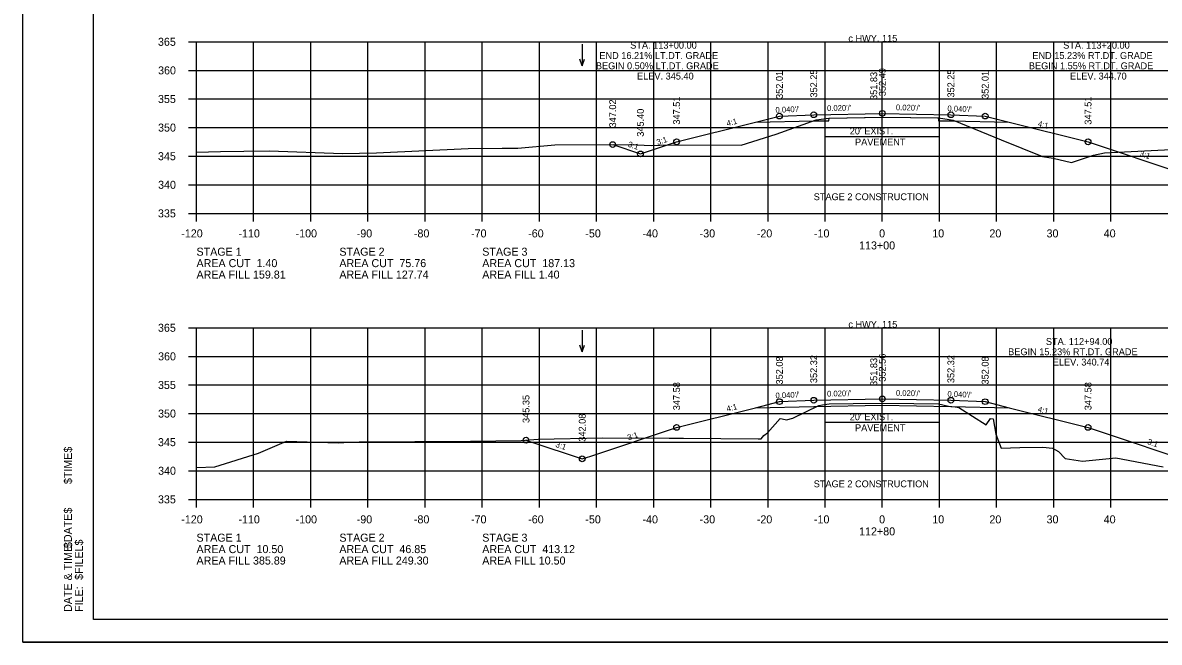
# Model space of a CAD drawing. Extents: x 1630712 to 1632516, y 782146 to 785403.
# Drawn here: x 1632182.6 to 1632381.4, y 784763.3 to 784871.6 of the extents above; entities that cross this region are included whole.
import ezdxf

# ---------------------------------------------------------------- set-up
doc = ezdxf.new("R2010")
doc.units = 0
for name, color, linetype in [('Default', 7, 'Continuous'), ('Notes', 7, 'Continuous'), ('R_Alt Surface', 7, 'Continuous'), ('R_Axis', 7, 'Continuous'), ('R_Axis Annot', 7, 'Continuous'), ('R_Border', 7, 'Continuous'), ('R_Exist Surface', 7, 'Continuous'), ('R_Fin Surface', 7, 'Continuous'), ('R_Grid', 7, 'Continuous'), ('R_No Plot', 7, 'Continuous'), ('R_Water Annot', 7, 'Continuous'), ('R_Xsect Elev', 7, 'Continuous'), ('R_Xsect Slope', 7, 'Continuous')]:
    doc.layers.add(name, color=color, linetype=linetype)

msp = doc.modelspace()

# ---------------------------------------------------------------- linework, layer by layer
at = {"layer": 'Notes'}
for p, q in [((1632322.96, 784850.05), (1632322.96, 784853.45)), ((1632342.96, 784850.05), (1632342.96, 784853.45)), ((1632322.96, 784851.75), (1632342.96, 784851.75)), ((1632322.96, 784800.08), (1632322.96, 784803.48)), ((1632342.96, 784800.08), (1632342.96, 784803.48)), ((1632322.96, 784801.78), (1632342.96, 784801.78))]:
    msp.add_line(p, q, dxfattribs=at)
at = {"layer": 'R_Alt Surface'}
for points in [[(1632310.79, 784854.27), (1632320.96, 784854.47), (1632323.63, 784854.52), (1632323.68, 784854.96), (1632333.09, 784855.14), (1632342.77, 784854.99), (1632342.82, 784854.52), (1632344.96, 784854.47), (1632355.14, 784854.27)], [(1632310.78, 784804.34), (1632320.96, 784804.55), (1632332.96, 784804.79), (1632344.96, 784804.55), (1632355.15, 784804.34)]]:
    msp.add_lwpolyline(points, dxfattribs=at)
at = {"layer": 'R_Axis'}
for p, q in [((1632211.56, 784868.31), (1632212.96, 784868.31)), ((1632212.96, 784838.31), (1632212.96, 784868.31)), ((1632211.56, 784863.31), (1632212.96, 784863.31)), ((1632211.56, 784858.31), (1632212.96, 784858.31)), ((1632211.56, 784853.31), (1632212.96, 784853.31)), ((1632211.56, 784848.31), (1632212.96, 784848.31)), ((1632211.56, 784843.31), (1632212.96, 784843.31)), ((1632211.56, 784838.31), (1632212.96, 784838.31)), ((1632212.96, 784838.31), (1632492.96, 784838.31)), ((1632212.96, 784836.91), (1632212.96, 784838.31)), ((1632222.96, 784836.91), (1632222.96, 784838.31)), ((1632232.96, 784836.91), (1632232.96, 784838.31)), ((1632242.96, 784836.91), (1632242.96, 784838.31)), ((1632252.96, 784836.91), (1632252.96, 784838.31)), ((1632262.96, 784836.91), (1632262.96, 784838.31)), ((1632272.96, 784836.91), (1632272.96, 784838.31)), ((1632282.96, 784836.91), (1632282.96, 784838.31)), ((1632292.96, 784836.91), (1632292.96, 784838.31)), ((1632302.96, 784836.91), (1632302.96, 784838.31)), ((1632312.96, 784836.91), (1632312.96, 784838.31)), ((1632322.96, 784836.91), (1632322.96, 784838.31)), ((1632332.96, 784836.91), (1632332.96, 784838.31)), ((1632342.96, 784836.91), (1632342.96, 784838.31)), ((1632352.96, 784836.91), (1632352.96, 784838.31)), ((1632362.96, 784836.91), (1632362.96, 784838.31)), ((1632372.96, 784836.91), (1632372.96, 784838.31)), ((1632211.56, 784818.31), (1632212.96, 784818.31)), ((1632212.96, 784788.31), (1632212.96, 784818.31)), ((1632211.56, 784813.31), (1632212.96, 784813.31)), ((1632211.56, 784808.31), (1632212.96, 784808.31)), ((1632211.56, 784803.31), (1632212.96, 784803.31)), ((1632211.56, 784798.31), (1632212.96, 784798.31)), ((1632211.56, 784793.31), (1632212.96, 784793.31)), ((1632211.56, 784788.31), (1632212.96, 784788.31)), ((1632212.96, 784788.31), (1632492.96, 784788.31)), ((1632212.96, 784786.91), (1632212.96, 784788.31)), ((1632222.96, 784786.91), (1632222.96, 784788.31)), ((1632232.96, 784786.91), (1632232.96, 784788.31)), ((1632242.96, 784786.91), (1632242.96, 784788.31)), ((1632252.96, 784786.91), (1632252.96, 784788.31)), ((1632262.96, 784786.91), (1632262.96, 784788.31)), ((1632272.96, 784786.91), (1632272.96, 784788.31)), ((1632282.96, 784786.91), (1632282.96, 784788.31)), ((1632292.96, 784786.91), (1632292.96, 784788.31)), ((1632302.96, 784786.91), (1632302.96, 784788.31)), ((1632312.96, 784786.91), (1632312.96, 784788.31)), ((1632322.96, 784786.91), (1632322.96, 784788.31)), ((1632332.96, 784786.91), (1632332.96, 784788.31)), ((1632342.96, 784786.91), (1632342.96, 784788.31)), ((1632352.96, 784786.91), (1632352.96, 784788.31)), ((1632362.96, 784786.91), (1632362.96, 784788.31)), ((1632372.96, 784786.91), (1632372.96, 784788.31))]:
    msp.add_line(p, q, dxfattribs=at)
at = {"layer": 'R_Border'}
for p, q in [((1632194.96, 784767.31), (1632194.96, 784972.77)), ((1632511.14, 784767.31), (1632194.96, 784767.31))]:
    msp.add_line(p, q, dxfattribs=at)
at = {"layer": 'R_Exist Surface'}
for points in [[(1632212.96, 784849.04), (1632217.18, 784849.11), (1632221.23, 784849.16), (1632225.71, 784849.22), (1632238.48, 784848.79), (1632244.48, 784848.88), (1632260.51, 784849.66), (1632266.47, 784849.7), (1632269.19, 784849.73), (1632275.65, 784850.32), (1632288.76, 784850.33), (1632292.5, 784850.16), (1632295.61, 784850.31), (1632308.29, 784850.23), (1632314.39, 784852.16), (1632321.39, 784854.67), (1632323.6, 784854.95), (1632323.68, 784854.96), (1632332.91, 784855.14), (1632333.09, 784855.14), (1632342.61, 784855), (1632342.77, 784854.99), (1632344.68, 784854.73), (1632345.34, 784854.6), (1632353.77, 784851.16), (1632361.01, 784848.26), (1632362.84, 784847.94), (1632366.08, 784847.22), (1632369.94, 784848.48), (1632371.82, 784848.92), (1632383.48, 784849.48)], [(1632212.96, 784793.87), (1632216.17, 784794), (1632223.79, 784796.41), (1632228.73, 784798.51), (1632237.75, 784798.21), (1632238.76, 784798.23), (1632241.44, 784798.36), (1632260.9, 784798.49), (1632269.78, 784798.59), (1632272.77, 784798.86), (1632284.02, 784799.04), (1632295.64, 784799.02), (1632298.16, 784799), (1632311.24, 784798.9), (1632311.76, 784798.9), (1632312.24, 784799.5), (1632312.88, 784799.92), (1632315.1, 784802.44), (1632315.42, 784802.41), (1632316.19, 784802.2), (1632317.31, 784802.51), (1632321.88, 784804.73), (1632322.47, 784804.81), (1632323.66, 784804.99), (1632327.84, 784805.06), (1632333.12, 784805.14), (1632338.45, 784805.07), (1632342.77, 784805.01), (1632344.56, 784804.63), (1632345.7, 784804.48), (1632346.37, 784804.36), (1632351.14, 784801.35), (1632351.91, 784802.42), (1632352.33, 784802.41), (1632352.84, 784799.71), (1632353.77, 784797.24), (1632357.05, 784797.38), (1632361.04, 784797.43), (1632362.76, 784797.28), (1632363.81, 784796.7), (1632364.98, 784795.46), (1632368, 784794.97), (1632373.84, 784795.54), (1632382.12, 784794.01)]]:
    msp.add_lwpolyline(points, dxfattribs=at)
at = {"layer": 'R_Fin Surface'}
for points in [[(1632285.78, 784850.33), (1632290.64, 784848.71), (1632296.96, 784850.82), (1632310.79, 784854.27), (1632314.96, 784855.32), (1632320.96, 784855.56), (1632332.96, 784855.8), (1632344.96, 784855.56), (1632350.96, 784855.32), (1632355.14, 784854.27), (1632368.96, 784850.82), (1632385.36, 784845.35), (1632385.37, 784845.35), (1632385.51, 784845.3), (1632386.53, 784844.96), (1632401.47, 784849.94), (1632401.78, 784850.05), (1632401.78, 784850.05), (1632402.54, 784850.3)], [(1632270.62, 784798.66), (1632271.44, 784798.39), (1632280.45, 784795.39), (1632281.94, 784795.88), (1632296.96, 784800.89), (1632310.78, 784804.34), (1632314.96, 784805.39), (1632320.96, 784805.63), (1632332.96, 784805.87), (1632344.96, 784805.63), (1632350.96, 784805.39), (1632355.15, 784804.34), (1632368.96, 784800.89), (1632389.23, 784794.13), (1632390.56, 784794.58)]]:
    msp.add_lwpolyline(points, dxfattribs=at)
at = {"layer": 'R_Grid'}
for p, q in [((1632212.96, 784868.31), (1632492.96, 784868.31)), ((1632212.96, 784838.31), (1632212.96, 784868.31)), ((1632222.96, 784838.31), (1632222.96, 784868.31)), ((1632232.96, 784838.31), (1632232.96, 784868.31)), ((1632242.96, 784838.31), (1632242.96, 784868.31)), ((1632252.96, 784838.31), (1632252.96, 784868.31)), ((1632262.96, 784838.31), (1632262.96, 784868.31)), ((1632272.96, 784838.31), (1632272.96, 784868.31)), ((1632282.96, 784838.31), (1632282.96, 784868.31)), ((1632292.96, 784838.31), (1632292.96, 784868.31)), ((1632302.96, 784838.31), (1632302.96, 784868.31)), ((1632312.96, 784838.31), (1632312.96, 784868.31)), ((1632322.96, 784838.31), (1632322.96, 784868.31)), ((1632332.96, 784838.31), (1632332.96, 784868.31)), ((1632342.96, 784838.31), (1632342.96, 784868.31)), ((1632352.96, 784838.31), (1632352.96, 784868.31)), ((1632362.96, 784838.31), (1632362.96, 784868.31)), ((1632372.96, 784838.31), (1632372.96, 784868.31)), ((1632212.96, 784863.31), (1632492.96, 784863.31)), ((1632212.96, 784858.31), (1632492.96, 784858.31)), ((1632212.96, 784853.31), (1632492.96, 784853.31)), ((1632212.96, 784848.31), (1632492.96, 784848.31)), ((1632212.96, 784843.31), (1632492.96, 784843.31)), ((1632212.96, 784838.31), (1632492.96, 784838.31)), ((1632212.96, 784818.31), (1632492.96, 784818.31)), ((1632212.96, 784788.31), (1632212.96, 784818.31)), ((1632222.96, 784788.31), (1632222.96, 784818.31)), ((1632232.96, 784788.31), (1632232.96, 784818.31)), ((1632242.96, 784788.31), (1632242.96, 784818.31)), ((1632252.96, 784788.31), (1632252.96, 784818.31)), ((1632262.96, 784788.31), (1632262.96, 784818.31)), ((1632272.96, 784788.31), (1632272.96, 784818.31)), ((1632282.96, 784788.31), (1632282.96, 784818.31)), ((1632292.96, 784788.31), (1632292.96, 784818.31)), ((1632302.96, 784788.31), (1632302.96, 784818.31)), ((1632312.96, 784788.31), (1632312.96, 784818.31)), ((1632322.96, 784788.31), (1632322.96, 784818.31)), ((1632332.96, 784788.31), (1632332.96, 784818.31)), ((1632342.96, 784788.31), (1632342.96, 784818.31)), ((1632352.96, 784788.31), (1632352.96, 784818.31)), ((1632362.96, 784788.31), (1632362.96, 784818.31)), ((1632372.96, 784788.31), (1632372.96, 784818.31)), ((1632212.96, 784813.31), (1632492.96, 784813.31)), ((1632212.96, 784808.31), (1632492.96, 784808.31)), ((1632212.96, 784803.31), (1632492.96, 784803.31)), ((1632212.96, 784798.31), (1632492.96, 784798.31)), ((1632212.96, 784793.31), (1632492.96, 784793.31)), ((1632212.96, 784788.31), (1632492.96, 784788.31))]:
    msp.add_line(p, q, dxfattribs=at)
at = {"layer": 'R_No Plot'}
msp.add_line((1632182.56, 784763.33), (1632515.9, 784763.33), dxfattribs=at)
msp.add_lwpolyline([(1632182.56, 784976.66), (1632515.9, 784976.66), (1632515.9, 784763.32), (1632182.56, 784763.32)], close=True, dxfattribs=at)
for centre in [(1632332.96, 784855.8), (1632314.96, 784855.32), (1632320.96, 784855.56), (1632344.96, 784855.56), (1632350.96, 784855.32), (1632285.78, 784850.33), (1632296.96, 784850.82), (1632368.96, 784850.82), (1632290.64, 784848.71), (1632314.96, 784805.39), (1632320.96, 784805.63), (1632332.96, 784805.87), (1632344.96, 784805.63), (1632350.96, 784805.39), (1632296.96, 784800.89), (1632368.96, 784800.89), (1632270.62, 784798.66), (1632280.45, 784795.39)]:
    msp.add_circle(centre, 0.5, dxfattribs=at)
at = {"layer": 'R_Water Annot'}
for p, q in [((1632280.45, 784867.88), (1632280.45, 784864.11)), ((1632280.45, 784864.11), (1632280.03, 784865.26)), ((1632280.45, 784864.11), (1632280.87, 784865.26)), ((1632280.45, 784817.88), (1632280.45, 784814.11)), ((1632280.45, 784814.11), (1632280.03, 784815.26)), ((1632280.45, 784814.11), (1632280.87, 784815.26))]:
    msp.add_line(p, q, dxfattribs=at)

# ---------------------------------------------------------------- texts
at = {"layer": 'Default'}
for s, height, p in [('$TIME$', 1.397, (1632191.16, 784790.98)), ('$DATE$', 1.397, (1632191.16, 784779.8)), ('DATE & TIME:', 1.3968, (1632191.16, 784768.63)), ('$FILEL$', 1.397, (1632193.08, 784774.22)), ('FILE: ', 1.397, (1632193.08, 784768.63))]:
    msp.add_text(s, height=height, rotation=90, dxfattribs=at).set_placement(p)
at = {"layer": 'Notes'}
for s, p in [('STA. 113+00.00', (1632288.85, 784867.11)), ('c HWY. 115', (1632327.02, 784868.31)), ('STA. 113+20.00', (1632364.61, 784867.11)), ('END 16.21% LT.DT. GRADE', (1632283.45, 784865.31)), ('END 15.23% RT.DT. GRADE', (1632359.21, 784865.31)), ('BEGIN 0.50% LT.DT. GRADE', (1632282.85, 784863.51)), ('BEGIN 1.55% RT.DT. GRADE', (1632358.61, 784863.51)), ('ELEV. 345.40', (1632290.05, 784861.71)), ('ELEV. 344.70', (1632365.81, 784861.71)), ("20' EXIST.", (1632327.26, 784852.11)), ('PAVEMENT', (1632328.19, 784850.19)), ('STAGE 2 CONSTRUCTION', (1632320.96, 784840.62)), ('c HWY. 115', (1632327.02, 784818.31)), ('STA. 112+94.00', (1632361.58, 784815.31)), ('BEGIN 15.23% RT.DT. GRADE', (1632354.98, 784813.51)), ('ELEV. 340.74', (1632362.79, 784811.71)), ("20' EXIST.", (1632327.26, 784802.14)), ('PAVEMENT', (1632328.19, 784800.22)), ('STAGE 2 CONSTRUCTION', (1632320.96, 784790.42))]:
    msp.add_text(s, height=1.2, dxfattribs=at).set_placement(p)
at = {"layer": 'R_Axis'}
for p in [(1632212.96, 784838.31), (1632212.96, 784788.31)]:
    msp.add_text('-', height=0.0001, dxfattribs=at).set_placement(p)
at = {"layer": 'R_Axis Annot'}
for s, p in [('365', (1632206.22, 784867.61)), ('360', (1632206.24, 784862.61)), ('355', (1632206.22, 784857.61)), ('350', (1632206.24, 784852.61)), ('345', (1632206.22, 784847.61)), ('340', (1632206.24, 784842.61)), ('335', (1632206.22, 784837.61)), ('-120', (1632210.3, 784834.11)), ('-110', (1632220.3, 784834.11)), ('-100', (1632230.3, 784834.11)), ('-90', (1632241, 784834.11)), ('-80', (1632251, 784834.11)), ('-70', (1632261, 784834.11)), ('-60', (1632271, 784834.11)), ('-50', (1632281, 784834.11)), ('-40', (1632291, 784834.11)), ('-30', (1632301, 784834.11)), ('-20', (1632311, 784834.11)), ('-10', (1632321, 784834.11)), ('0', (1632332.4, 784834.11)), ('10', (1632341.7, 784834.11)), ('20', (1632351.7, 784834.11)), ('30', (1632361.7, 784834.11)), ('40', (1632371.7, 784834.11)), ('STAGE 1', (1632212.96, 784830.91)), ('STAGE 2', (1632237.96, 784830.91)), ('STAGE 3', (1632262.96, 784830.91)), ('113+00', (1632328.9, 784832.01)), ('AREA CUT  1.40', (1632212.96, 784828.91)), ('AREA CUT  75.76', (1632237.96, 784828.91)), ('AREA CUT  187.13', (1632262.96, 784828.91)), ('AREA FILL 159.81', (1632212.96, 784826.91)), ('AREA FILL 127.74', (1632237.96, 784826.91)), ('AREA FILL 1.40', (1632262.96, 784826.91)), ('365', (1632206.22, 784817.61)), ('360', (1632206.24, 784812.61)), ('355', (1632206.22, 784807.61)), ('350', (1632206.24, 784802.61)), ('345', (1632206.22, 784797.61)), ('340', (1632206.24, 784792.61)), ('335', (1632206.22, 784787.61)), ('-120', (1632210.3, 784784.11)), ('-110', (1632220.3, 784784.11)), ('-100', (1632230.3, 784784.11)), ('-90', (1632241, 784784.11)), ('-80', (1632251, 784784.11)), ('-70', (1632261, 784784.11)), ('-60', (1632271, 784784.11)), ('-50', (1632281, 784784.11)), ('-40', (1632291, 784784.11)), ('-30', (1632301, 784784.11)), ('-20', (1632311, 784784.11)), ('-10', (1632321, 784784.11)), ('0', (1632332.4, 784784.11)), ('10', (1632341.7, 784784.11)), ('20', (1632351.7, 784784.11)), ('30', (1632361.7, 784784.11)), ('40', (1632371.7, 784784.11)), ('112+80', (1632328.9, 784782.01)), ('STAGE 1', (1632212.96, 784780.91)), ('STAGE 2', (1632237.96, 784780.91)), ('STAGE 3', (1632262.96, 784780.91)), ('AREA CUT  10.50', (1632212.96, 784778.91)), ('AREA CUT  46.85', (1632237.96, 784778.91)), ('AREA CUT  413.12', (1632262.96, 784778.91)), ('AREA FILL 385.89', (1632212.96, 784776.91)), ('AREA FILL 249.30', (1632237.96, 784776.91)), ('AREA FILL 10.50', (1632262.96, 784776.91))]:
    msp.add_text(s, height=1.4, dxfattribs=at).set_placement(p)
at = {"layer": 'R_Xsect Elev'}
for s, p in [('352.01', (1632315.56, 784858.32)), ('352.25', (1632321.56, 784858.56)), ('351.83', (1632332.06, 784858.14)), ('352.49', (1632333.56, 784858.8)), ('352.25', (1632345.56, 784858.56)), ('352.01', (1632351.56, 784858.32)), ('347.51', (1632297.56, 784853.82)), ('347.51', (1632369.56, 784853.82)), ('347.02', (1632286.38, 784853.33)), ('345.40', (1632291.24, 784851.71)), ('352.08', (1632315.56, 784808.39)), ('352.32', (1632321.56, 784808.63)), ('351.83', (1632332.06, 784808.13)), ('352.56', (1632333.56, 784808.87)), ('352.32', (1632345.56, 784808.63)), ('352.08', (1632351.56, 784808.39)), ('347.58', (1632297.56, 784803.89)), ('347.58', (1632369.56, 784803.89)), ('345.35', (1632271.22, 784801.66)), ('342.08', (1632281.05, 784798.39))]:
    msp.add_text(s, height=1.2, rotation=90, dxfattribs=at).set_placement(p)
at = {"layer": 'R_Xsect Slope'}
for s, rotation, p in [("0.040'/'", 2.2906, (1632314.29, 784855.89)), ("0.020'/'", 1.1458, (1632323.3, 784856.2)), ("0.020'/'", 358.8542, (1632335.33, 784856.35)), ("0.040'/'", 357.7094, (1632344.34, 784856.18)), ('4:1', 14.0362, (1632305.84, 784853.55)), ('4:1', 345.9638, (1632360.09, 784853.55)), ('3:1', 341.5651, (1632288.37, 784849.99)), ('3:1', 18.4349, (1632293.65, 784850.24)), ('3:1', 341.5651, (1632377.9, 784848.36)), ("0.040'/'", 2.2906, (1632314.29, 784805.96)), ("0.020'/'", 1.1458, (1632323.3, 784806.28)), ("0.020'/'", 358.8542, (1632335.33, 784806.42)), ("0.040'/'", 357.7094, (1632344.34, 784806.26)), ('4:1', 14.0362, (1632305.84, 784803.63)), ('4:1', 345.9638, (1632360.09, 784803.63)), ('3:1', 18.4349, (1632288.55, 784798.61)), ('3:1', 341.5651, (1632379.26, 784797.99)), ('3:1', 341.5651, (1632275.7, 784797.5))]:
    msp.add_text(s, height=1, rotation=rotation, dxfattribs=at).set_placement(p)

doc.saveas('drawing.dxf')
